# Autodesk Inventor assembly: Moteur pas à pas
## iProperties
Author: Philippe
Created: 2002-08
Part Number: Moteur pas à pas
Document SubType Name: Assemblage
Designer: Philippe
Control State: 0
Master: False
Checked Out: False
PropertySet Name: Design Tracking Control
Shininess: 41.0
Angle Display Precision: 2
Document Length Units: 11269
Document Angle Units: 11283
Document Time Units: 11279
Document Mass Units: 11290
Document Length Units Precision: 3
Document Angle Units Precision: 2
Compacted: False
PropertySet Name: _Private Model Information
Density: 0.0
Volumn: 0.0
Area: 0.0
PropertySet Name: Model Information
